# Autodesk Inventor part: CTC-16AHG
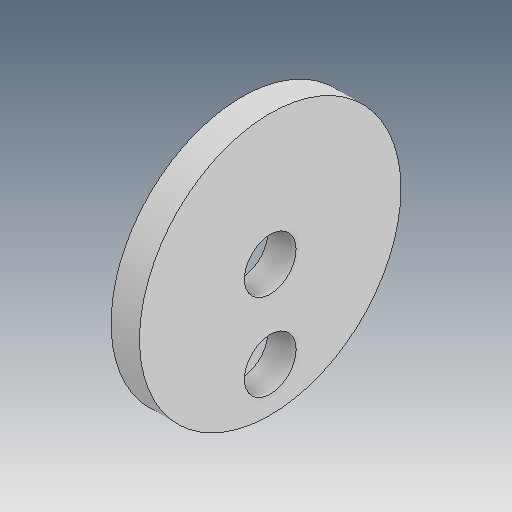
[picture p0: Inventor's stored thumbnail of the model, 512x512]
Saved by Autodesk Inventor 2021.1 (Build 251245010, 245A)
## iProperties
Created: 2018-08
Part Number: CTC-16AHG
Material: Ogólny
Document SubType Name: Modeling
Designer: user
Density: 1 g/cm^3
Appearance: Domyślna
Author: user
Revision Number: ÈÎºÎ
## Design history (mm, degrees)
feature "ÊäÈë1"
node "Bryła1"
